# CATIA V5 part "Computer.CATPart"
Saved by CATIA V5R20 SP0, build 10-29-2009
Part number: Part3
Bounding box of the stored display mesh (mm): x -59.638 to 145.423, y 0 to 920, z -59.638 to 145.423
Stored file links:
  C:\Users\HP\Downloads\Catia Project\Catia Project\Computer.CATPart
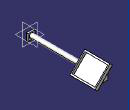
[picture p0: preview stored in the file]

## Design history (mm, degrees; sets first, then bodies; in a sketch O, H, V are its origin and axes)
Body1 (main body)
  Sketch1 on zx-plane, origin (0, 0, 0), H (-1, 0, 0), V (0, 0, 1)
    line L1 (40, 40) -> (40, -40)
    line L2 (40, -40) -> (-40, -40)
    line L3 (-40, -40) -> (-40, 40)
    line L4 (-40, 40) -> (40, 40)
  Pad1: profile Sketch1, direction (0, 1, 0), length 20
  Sketch2 on end face of Pad1, origin (0, 20, 0), H (-1, 0, 0), V (0, 0, 1)
    circle A1 centre (0, 0) radius 27.5
  Pad2: profile Sketch2, direction (0, 1, 0), length 650
  Sketch3 on end face of Pad2, origin (0, 670, 0), H (-1, 0, 0), V (0, 0, 1)
    line L1 (57.5, 57.5) -> (57.5, -57.5)
    line L2 (57.5, -57.5) -> (-57.5, -57.5)
    line L3 (-57.5, -57.5) -> (-57.5, 0)
    line L4 (0, 57.5) -> (57.5, 57.5)
    line L5 (-57.5, 0) -> (0, 57.5)
  Pad3: profile Sketch3, direction (0, 1, 0), length 200
  Sketch4 on face of Pad3 from Sketch3.L5, origin (28.75, 0, 28.75), H (0, 1, 0), V (-0.7071, 0, 0.7071)
    point P1 (770, 0)
    line L1 (920, 125) -> (920, -125)
    line L2 (920, -125) -> (620, -125)
    line L3 (620, -125) -> (620, 125)
    line L4 (620, 125) -> (920, 125)
  Pad4: profile Sketch4, direction (0.7071, 0, 0.7071), length 40
  Sketch5 on end face of Pad4, origin (57.0343, 0, 57.0343), H (0, 1, 0), V (-0.7071, 0, 0.7071)
    point P1 (770, 0)
    line L1 (908, 107.5) -> (908, -107.5)
    line L2 (908, -107.5) -> (632, -107.5)
    line L3 (632, -107.5) -> (632, 107.5)
    line L4 (632, 107.5) -> (908, 107.5)
  Pocket1: profile Sketch5, direction (-0.7071, 0, -0.7071), length 30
